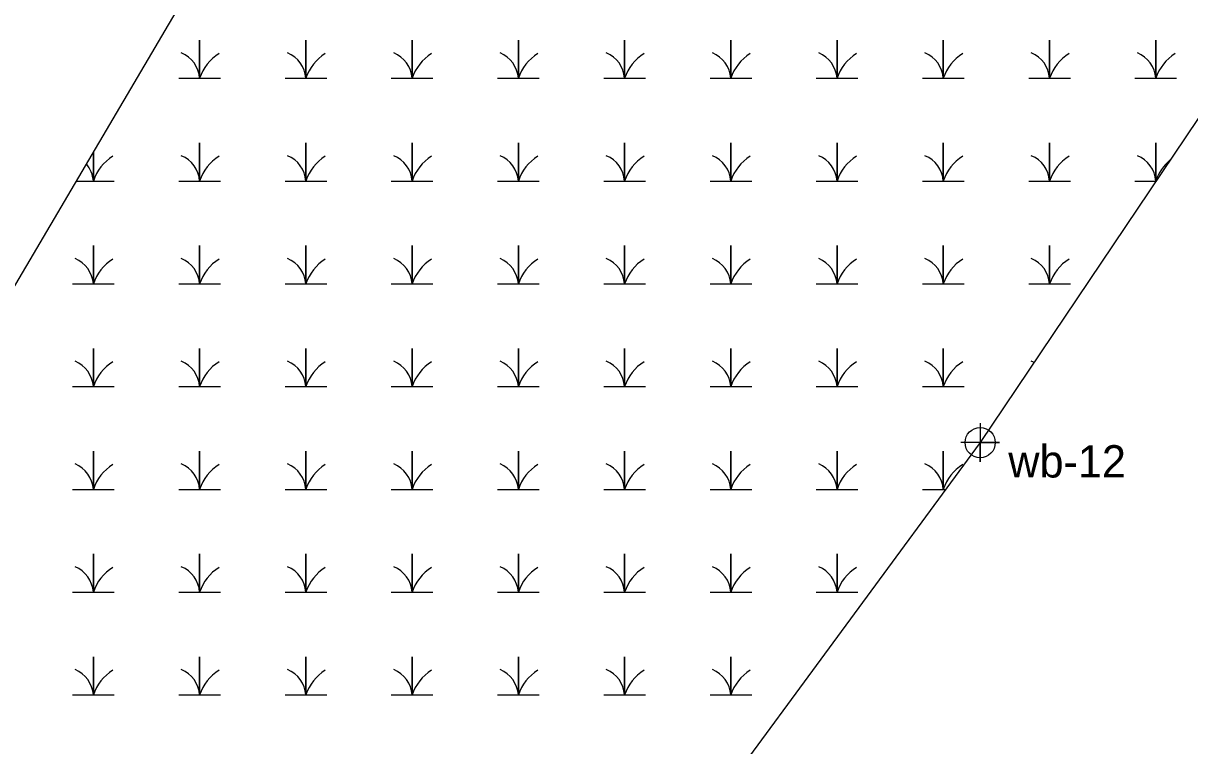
# Model space of a CAD drawing. Extents: x 2379288 to 2381905, y 330670 to 333511.
# Drawn here: x 2379849.1 to 2380029.7, y 331753.1 to 331864.9 of the extents above; entities that cross this region are included whole.
import ezdxf

# ---------------------------------------------------------------- set-up
doc = ezdxf.new("R2010")
doc.units = 0
for name, color, linetype in [('Default', 7, 'Continuous'), ('Exist Environmental Wetland Boundary', 7, 'Continuous'), ('Exist Environmental Wetland Boundary Cogo Number', 7, 'Continuous'), ('Exist Environmental Wetland Boundary Cogo Point CELL', 7, 'Continuous'), ('Exist Hydro Swamp or Marsh', 7, 'Continuous')]:
    doc.layers.add(name, color=color, linetype=linetype)

msp = doc.modelspace()

# ---------------------------------------------------------------- linework, layer by layer
at = {"layer": 'Default'}
msp.add_lwpolyline([(2380453.94, 332065.55), (2379632.78, 330670.47), (2379288.07, 330873.37), (2380109.3, 332268.58)], dxfattribs=at)
at = {"layer": 'Exist Environmental Wetland Boundary'}
msp.add_lwpolyline([(2380130.29, 332029.9), (2380102.32, 331972.59), (2380055.88, 331898.56), (2380034.74, 331855.71), (2379997.28, 331799.99), (2379955.67, 331743.45), (2379938.98, 331697.47), (2379905.07, 331626.66), (2379844.93, 331533.46), (2379815.25, 331542.18), (2379791.29, 331555.41), (2379761.99, 331575.7), (2379733.64, 331601.14), (2379721.48, 331609.71)], dxfattribs=at)
at = {"layer": 'Exist Environmental Wetland Boundary Cogo Point CELL'}
msp.add_lwpolyline([(2379997.28, 331802.99), (2379997.28, 331796.99), (2379997.28, 331799.99), (2380000.28, 331799.99), (2379994.28, 331799.99)], dxfattribs=at)
msp.add_circle((2379997.28, 331799.99), 2.34, dxfattribs=at)
at = {"layer": 'Exist Hydro Swamp or Marsh'}
for points in [[(2379873.19, 331856.42), (2379876.42, 331856.42), (2379876.42, 331862.34), (2379876.42, 331856.42), (2379879.64, 331856.42)], [(2379889.64, 331856.42), (2379892.87, 331856.42), (2379892.87, 331862.34), (2379892.87, 331856.42), (2379896.09, 331856.42)], [(2379906.09, 331856.42), (2379909.32, 331856.42), (2379909.32, 331862.34), (2379909.32, 331856.42), (2379912.54, 331856.42)], [(2379922.54, 331856.42), (2379925.77, 331856.42), (2379925.77, 331862.34), (2379925.77, 331856.42), (2379928.99, 331856.42)], [(2379938.99, 331856.42), (2379942.22, 331856.42), (2379942.22, 331862.34), (2379942.22, 331856.42), (2379945.45, 331856.42)], [(2379955.45, 331856.42), (2379958.67, 331856.42), (2379958.67, 331862.34), (2379958.67, 331856.42), (2379961.9, 331856.42)], [(2379971.9, 331856.42), (2379975.12, 331856.42), (2379975.12, 331862.34), (2379975.12, 331856.42), (2379978.35, 331856.42)], [(2379988.35, 331856.42), (2379991.57, 331856.42), (2379991.57, 331862.34), (2379991.57, 331856.42), (2379994.8, 331856.42)], [(2380004.8, 331856.42), (2380008.03, 331856.42), (2380008.03, 331862.34), (2380008.03, 331856.42), (2380011.25, 331856.42)], [(2380021.25, 331856.42), (2380024.48, 331856.42), (2380024.48, 331862.34), (2380024.48, 331856.42), (2380027.7, 331856.42)], [(2379873.19, 331840.51), (2379876.42, 331840.51), (2379876.42, 331846.42), (2379876.42, 331840.51), (2379879.64, 331840.51)], [(2379889.64, 331840.51), (2379892.87, 331840.51), (2379892.87, 331846.42), (2379892.87, 331840.51), (2379896.09, 331840.51)], [(2379906.09, 331840.51), (2379909.32, 331840.51), (2379909.32, 331846.42), (2379909.32, 331840.51), (2379912.54, 331840.51)], [(2379922.54, 331840.51), (2379925.77, 331840.51), (2379925.77, 331846.42), (2379925.77, 331840.51), (2379928.99, 331840.51)], [(2379938.99, 331840.51), (2379942.22, 331840.51), (2379942.22, 331846.42), (2379942.22, 331840.51), (2379945.45, 331840.51)], [(2379955.45, 331840.51), (2379958.67, 331840.51), (2379958.67, 331846.42), (2379958.67, 331840.51), (2379961.9, 331840.51)], [(2379971.9, 331840.51), (2379975.12, 331840.51), (2379975.12, 331846.42), (2379975.12, 331840.51), (2379978.35, 331840.51)], [(2379988.35, 331840.51), (2379991.57, 331840.51), (2379991.57, 331846.42), (2379991.57, 331840.51), (2379994.8, 331840.51)], [(2380004.8, 331840.51), (2380008.03, 331840.51), (2380008.03, 331846.42), (2380008.03, 331840.51), (2380011.25, 331840.51)], [(2380021.25, 331840.51), (2380024.48, 331840.51), (2380024.48, 331846.42), (2380024.48, 331840.51), (2380024.52, 331840.51)], [(2379857.33, 331840.51), (2379859.96, 331840.51), (2379859.96, 331844.98)], [(2379859.96, 331844.98), (2379859.96, 331840.51), (2379863.19, 331840.51)], [(2379856.74, 331824.59), (2379859.96, 331824.59), (2379859.96, 331830.51), (2379859.96, 331824.59), (2379863.19, 331824.59)], [(2379873.19, 331824.59), (2379876.42, 331824.59), (2379876.42, 331830.51), (2379876.42, 331824.59), (2379879.64, 331824.59)], [(2379889.64, 331824.59), (2379892.87, 331824.59), (2379892.87, 331830.51), (2379892.87, 331824.59), (2379896.09, 331824.59)], [(2379906.09, 331824.59), (2379909.32, 331824.59), (2379909.32, 331830.51), (2379909.32, 331824.59), (2379912.54, 331824.59)], [(2379922.54, 331824.59), (2379925.77, 331824.59), (2379925.77, 331830.51), (2379925.77, 331824.59), (2379928.99, 331824.59)], [(2379938.99, 331824.59), (2379942.22, 331824.59), (2379942.22, 331830.51), (2379942.22, 331824.59), (2379945.45, 331824.59)], [(2379955.45, 331824.59), (2379958.67, 331824.59), (2379958.67, 331830.51), (2379958.67, 331824.59), (2379961.9, 331824.59)], [(2379971.9, 331824.59), (2379975.12, 331824.59), (2379975.12, 331830.51), (2379975.12, 331824.59), (2379978.35, 331824.59)], [(2379988.35, 331824.59), (2379991.57, 331824.59), (2379991.57, 331830.51), (2379991.57, 331824.59), (2379994.8, 331824.59)], [(2380004.8, 331824.59), (2380008.03, 331824.59), (2380008.03, 331830.51), (2380008.03, 331824.59), (2380011.25, 331824.59)], [(2379856.74, 331808.67), (2379859.96, 331808.67), (2379859.96, 331814.59), (2379859.96, 331808.67), (2379863.19, 331808.67)], [(2379873.19, 331808.67), (2379876.42, 331808.67), (2379876.42, 331814.59), (2379876.42, 331808.67), (2379879.64, 331808.67)], [(2379889.64, 331808.67), (2379892.87, 331808.67), (2379892.87, 331814.59), (2379892.87, 331808.67), (2379896.09, 331808.67)], [(2379906.09, 331808.67), (2379909.32, 331808.67), (2379909.32, 331814.59), (2379909.32, 331808.67), (2379912.54, 331808.67)], [(2379922.54, 331808.67), (2379925.77, 331808.67), (2379925.77, 331814.59), (2379925.77, 331808.67), (2379928.99, 331808.67)], [(2379938.99, 331808.67), (2379942.22, 331808.67), (2379942.22, 331814.59), (2379942.22, 331808.67), (2379945.45, 331808.67)], [(2379955.45, 331808.67), (2379958.67, 331808.67), (2379958.67, 331814.59), (2379958.67, 331808.67), (2379961.9, 331808.67)], [(2379971.9, 331808.67), (2379975.12, 331808.67), (2379975.12, 331814.59), (2379975.12, 331808.67), (2379978.35, 331808.67)], [(2379988.35, 331808.67), (2379991.57, 331808.67), (2379991.57, 331814.59), (2379991.57, 331808.67), (2379994.8, 331808.67)], [(2379856.74, 331792.75), (2379859.96, 331792.75), (2379859.96, 331798.67), (2379859.96, 331792.75), (2379863.19, 331792.75)], [(2379873.19, 331792.75), (2379876.42, 331792.75), (2379876.42, 331798.67), (2379876.42, 331792.75), (2379879.64, 331792.75)], [(2379889.64, 331792.75), (2379892.87, 331792.75), (2379892.87, 331798.67), (2379892.87, 331792.75), (2379896.09, 331792.75)], [(2379906.09, 331792.75), (2379909.32, 331792.75), (2379909.32, 331798.67), (2379909.32, 331792.75), (2379912.54, 331792.75)], [(2379922.54, 331792.75), (2379925.77, 331792.75), (2379925.77, 331798.67), (2379925.77, 331792.75), (2379928.99, 331792.75)], [(2379938.99, 331792.75), (2379942.22, 331792.75), (2379942.22, 331798.67), (2379942.22, 331792.75), (2379945.45, 331792.75)], [(2379955.45, 331792.75), (2379958.67, 331792.75), (2379958.67, 331798.67), (2379958.67, 331792.75), (2379961.9, 331792.75)], [(2379971.9, 331792.75), (2379975.12, 331792.75), (2379975.12, 331798.67), (2379975.12, 331792.75), (2379978.35, 331792.75)], [(2379988.35, 331792.75), (2379991.57, 331792.75), (2379991.57, 331798.67), (2379991.57, 331792.75), (2379991.95, 331792.75)], [(2379856.74, 331776.83), (2379859.96, 331776.83), (2379859.96, 331782.75), (2379859.96, 331776.83), (2379863.19, 331776.83)], [(2379873.19, 331776.83), (2379876.42, 331776.83), (2379876.42, 331782.75), (2379876.42, 331776.83), (2379879.64, 331776.83)], [(2379889.64, 331776.83), (2379892.87, 331776.83), (2379892.87, 331782.75), (2379892.87, 331776.83), (2379896.09, 331776.83)], [(2379906.09, 331776.83), (2379909.32, 331776.83), (2379909.32, 331782.75), (2379909.32, 331776.83), (2379912.54, 331776.83)], [(2379922.54, 331776.83), (2379925.77, 331776.83), (2379925.77, 331782.75), (2379925.77, 331776.83), (2379928.99, 331776.83)], [(2379938.99, 331776.83), (2379942.22, 331776.83), (2379942.22, 331782.75), (2379942.22, 331776.83), (2379945.45, 331776.83)], [(2379955.45, 331776.83), (2379958.67, 331776.83), (2379958.67, 331782.75), (2379958.67, 331776.83), (2379961.9, 331776.83)], [(2379971.9, 331776.83), (2379975.12, 331776.83), (2379975.12, 331782.75), (2379975.12, 331776.83), (2379978.35, 331776.83)], [(2379856.74, 331760.92), (2379859.96, 331760.92), (2379859.96, 331766.83), (2379859.96, 331760.92), (2379863.19, 331760.92)], [(2379873.19, 331760.92), (2379876.42, 331760.92), (2379876.42, 331766.83), (2379876.42, 331760.92), (2379879.64, 331760.92)], [(2379889.64, 331760.92), (2379892.87, 331760.92), (2379892.87, 331766.83), (2379892.87, 331760.92), (2379896.09, 331760.92)], [(2379906.09, 331760.92), (2379909.32, 331760.92), (2379909.32, 331766.83), (2379909.32, 331760.92), (2379912.54, 331760.92)], [(2379922.54, 331760.92), (2379925.77, 331760.92), (2379925.77, 331766.83), (2379925.77, 331760.92), (2379928.99, 331760.92)], [(2379938.99, 331760.92), (2379942.22, 331760.92), (2379942.22, 331766.83), (2379942.22, 331760.92), (2379945.45, 331760.92)], [(2379955.45, 331760.92), (2379958.67, 331760.92), (2379958.67, 331766.83), (2379958.67, 331760.92), (2379961.9, 331760.92)]]:
    msp.add_lwpolyline(points, dxfattribs=at)
for centre, radius, start, end in [((2379871.82, 331856.09), 4.61, 4.1403, 67.535), ((2379883.26, 331854.15), 7.21, 122.1274, 161.6222), ((2379888.27, 331856.09), 4.61, 4.1403, 67.535), ((2379899.71, 331854.15), 7.21, 122.1274, 161.6222), ((2379904.72, 331856.09), 4.61, 4.1403, 67.535), ((2379916.16, 331854.15), 7.21, 122.1274, 161.6222), ((2379921.17, 331856.09), 4.61, 4.1403, 67.535), ((2379932.61, 331854.15), 7.21, 122.1274, 161.6222), ((2379937.62, 331856.09), 4.61, 4.1403, 67.535), ((2379949.06, 331854.15), 7.21, 122.1274, 161.6222), ((2379954.07, 331856.09), 4.61, 4.1403, 67.535), ((2379965.51, 331854.15), 7.21, 122.1274, 161.6222), ((2379970.52, 331856.09), 4.61, 4.1403, 67.535), ((2379981.96, 331854.15), 7.21, 122.1274, 161.6222), ((2379986.97, 331856.09), 4.61, 4.1403, 67.535), ((2379998.41, 331854.15), 7.21, 122.1274, 161.6222), ((2380003.43, 331856.09), 4.61, 4.1403, 67.535), ((2380014.87, 331854.15), 7.21, 122.1274, 161.6222), ((2380019.88, 331856.09), 4.61, 4.1403, 67.535), ((2380031.32, 331854.15), 7.21, 122.1274, 161.6222), ((2379866.81, 331838.23), 7.21, 122.1274, 161.6222), ((2379871.82, 331840.17), 4.61, 4.1403, 67.535), ((2379883.26, 331838.23), 7.21, 122.1274, 161.6222), ((2379888.27, 331840.17), 4.61, 4.1403, 67.535), ((2379899.71, 331838.23), 7.21, 122.1274, 161.6222), ((2379904.72, 331840.17), 4.61, 4.1403, 67.535), ((2379916.16, 331838.23), 7.21, 122.1274, 161.6222), ((2379921.17, 331840.17), 4.61, 4.1403, 67.535), ((2379932.61, 331838.23), 7.21, 122.1274, 161.6222), ((2379937.62, 331840.17), 4.61, 4.1403, 67.535), ((2379949.06, 331838.23), 7.21, 122.1274, 161.6222), ((2379954.07, 331840.17), 4.61, 4.1403, 67.535), ((2379965.51, 331838.23), 7.21, 122.1274, 161.6222), ((2379970.52, 331840.17), 4.61, 4.1403, 67.535), ((2379981.96, 331838.23), 7.21, 122.1274, 161.6222), ((2379986.97, 331840.17), 4.61, 4.1403, 67.535), ((2379998.41, 331838.23), 7.21, 122.1274, 161.6222), ((2380003.43, 331840.17), 4.61, 4.1403, 67.535), ((2380014.87, 331838.23), 7.21, 122.1274, 161.6222), ((2380019.88, 331840.17), 4.61, 4.1403, 67.535), ((2379855.36, 331840.17), 4.61, 4.1403, 40.2174), ((2380031.32, 331838.23), 7.21, 129.6349, 161.6222), ((2379855.36, 331824.25), 4.61, 4.1403, 67.535), ((2379866.81, 331822.31), 7.21, 122.1274, 161.6222), ((2379871.82, 331824.25), 4.61, 4.1403, 67.535), ((2379883.26, 331822.31), 7.21, 122.1274, 161.6222), ((2379888.27, 331824.25), 4.61, 4.1403, 67.535), ((2379899.71, 331822.31), 7.21, 122.1274, 161.6222), ((2379904.72, 331824.25), 4.61, 4.1403, 67.535), ((2379916.16, 331822.31), 7.21, 122.1274, 161.6222), ((2379921.17, 331824.25), 4.61, 4.1403, 67.535), ((2379932.61, 331822.31), 7.21, 122.1274, 161.6222), ((2379937.62, 331824.25), 4.61, 4.1403, 67.535), ((2379949.06, 331822.31), 7.21, 122.1274, 161.6222), ((2379954.07, 331824.25), 4.61, 4.1403, 67.535), ((2379965.51, 331822.31), 7.21, 122.1274, 161.6222), ((2379970.52, 331824.25), 4.61, 4.1403, 67.535), ((2379981.96, 331822.31), 7.21, 122.1274, 161.6222), ((2379986.97, 331824.25), 4.61, 4.1403, 67.535), ((2379998.41, 331822.31), 7.21, 122.1274, 161.6222), ((2380003.43, 331824.25), 4.61, 4.1403, 67.535), ((2380014.87, 331822.31), 7.21, 122.1274, 161.6222), ((2379855.36, 331808.34), 4.61, 4.1403, 67.535), ((2379866.81, 331806.4), 7.21, 122.1274, 161.6222), ((2379871.82, 331808.34), 4.61, 4.1403, 67.535), ((2379883.26, 331806.4), 7.21, 122.1274, 161.6222), ((2379888.27, 331808.34), 4.61, 4.1403, 67.535), ((2379899.71, 331806.4), 7.21, 122.1274, 161.6222), ((2379904.72, 331808.34), 4.61, 4.1403, 67.535), ((2379916.16, 331806.4), 7.21, 122.1274, 161.6222), ((2379921.17, 331808.34), 4.61, 4.1403, 67.535), ((2379932.61, 331806.4), 7.21, 122.1274, 161.6222), ((2379937.62, 331808.34), 4.61, 4.1403, 67.535), ((2379949.06, 331806.4), 7.21, 122.1274, 161.6222), ((2379954.07, 331808.34), 4.61, 4.1403, 67.535), ((2379965.51, 331806.4), 7.21, 122.1274, 161.6222), ((2379970.52, 331808.34), 4.61, 4.1403, 67.535), ((2379981.96, 331806.4), 7.21, 122.1274, 161.6222), ((2379986.97, 331808.34), 4.61, 4.1403, 67.535), ((2379998.41, 331806.4), 7.21, 122.1274, 161.6222), ((2380003.43, 331808.34), 4.61, 61.6167, 67.535), ((2379855.36, 331792.42), 4.61, 4.1403, 67.535), ((2379866.81, 331790.48), 7.21, 122.1274, 161.6222), ((2379871.82, 331792.42), 4.61, 4.1403, 67.535), ((2379883.26, 331790.48), 7.21, 122.1274, 161.6222), ((2379888.27, 331792.42), 4.61, 4.1403, 67.535), ((2379899.71, 331790.48), 7.21, 122.1274, 161.6222), ((2379904.72, 331792.42), 4.61, 4.1403, 67.535), ((2379916.16, 331790.48), 7.21, 122.1274, 161.6222), ((2379921.17, 331792.42), 4.61, 4.1403, 67.535), ((2379932.61, 331790.48), 7.21, 122.1274, 161.6222), ((2379937.62, 331792.42), 4.61, 4.1403, 67.535), ((2379949.06, 331790.48), 7.21, 122.1274, 161.6222), ((2379954.07, 331792.42), 4.61, 4.1403, 67.535), ((2379965.51, 331790.48), 7.21, 122.1274, 161.6222), ((2379970.52, 331792.42), 4.61, 4.1403, 67.535), ((2379981.96, 331790.48), 7.21, 122.1274, 161.6222), ((2379986.97, 331792.42), 4.61, 4.1403, 67.535), ((2379998.41, 331790.48), 7.21, 122.1274, 161.6222), ((2379855.36, 331776.5), 4.61, 4.1403, 67.535), ((2379866.81, 331774.56), 7.21, 122.1274, 161.6222), ((2379871.82, 331776.5), 4.61, 4.1403, 67.535), ((2379883.26, 331774.56), 7.21, 122.1274, 161.6222), ((2379888.27, 331776.5), 4.61, 4.1403, 67.535), ((2379899.71, 331774.56), 7.21, 122.1274, 161.6222), ((2379904.72, 331776.5), 4.61, 4.1403, 67.535), ((2379916.16, 331774.56), 7.21, 122.1274, 161.6222), ((2379921.17, 331776.5), 4.61, 4.1403, 67.535), ((2379932.61, 331774.56), 7.21, 122.1274, 161.6222), ((2379937.62, 331776.5), 4.61, 4.1403, 67.535), ((2379949.06, 331774.56), 7.21, 122.1274, 161.6222), ((2379954.07, 331776.5), 4.61, 4.1403, 67.535), ((2379965.51, 331774.56), 7.21, 122.1274, 161.6222), ((2379970.52, 331776.5), 4.61, 4.1403, 67.535), ((2379981.96, 331774.56), 7.21, 122.1274, 161.6222), ((2379855.36, 331760.58), 4.61, 4.1403, 67.535), ((2379866.81, 331758.64), 7.21, 122.1274, 161.6222), ((2379871.82, 331760.58), 4.61, 4.1403, 67.535), ((2379883.26, 331758.64), 7.21, 122.1274, 161.6222), ((2379888.27, 331760.58), 4.61, 4.1403, 67.535), ((2379899.71, 331758.64), 7.21, 122.1274, 161.6222), ((2379904.72, 331760.58), 4.61, 4.1403, 67.535), ((2379916.16, 331758.64), 7.21, 122.1274, 161.6222), ((2379921.17, 331760.58), 4.61, 4.1403, 67.535), ((2379932.61, 331758.64), 7.21, 122.1274, 161.6222), ((2379937.62, 331760.58), 4.61, 4.1403, 67.535), ((2379949.06, 331758.64), 7.21, 122.1274, 161.6222), ((2379954.07, 331760.58), 4.61, 4.1403, 67.535), ((2379965.51, 331758.64), 7.21, 122.1274, 161.6222)]:
    msp.add_arc(centre, radius, start, end, dxfattribs=at)

# ---------------------------------------------------------------- texts
at = {"layer": 'Exist Environmental Wetland Boundary Cogo Number'}
msp.add_text('wb-12', height=5, dxfattribs=at).set_placement((2380001.64, 331794.59))

doc.saveas('drawing.dxf')
